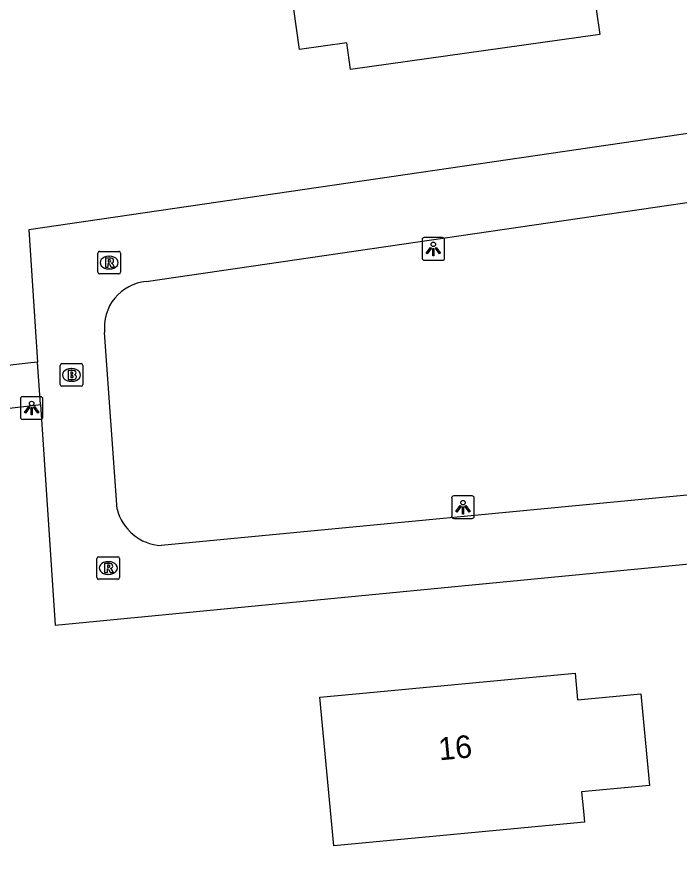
# Model space of a CAD drawing. Extents: x 162675 to 163482, y 379761 to 381227.
# Drawn here: x 163063.15 to 163092.42, y 380634.64 to 380672.29 of the extents above; entities that cross this region are included whole.
import ezdxf

# ---------------------------------------------------------------- set-up
doc = ezdxf.new("R2010")
doc.units = 0
for name, color, linetype in [('IMGEO_Brandkraan', 7, 'Continuous'), ('IMGEO_Lichtpunt', 7, 'Continuous'), ('IMGEO_Pand', 7, 'Continuous'), ('IMGEO_Pand_nummerreeks', 7, 'Continuous'), ('IMGEO_Rijbaan_lokaal_open', 7, 'Continuous'), ('IMGEO_Rioolput', 7, 'Continuous'), ('IMGEO_Voetpad_open', 7, 'Continuous')]:
    doc.layers.add(name, color=color, linetype=linetype)

msp = doc.modelspace()

# ---------------------------------------------------------------- linework, layer by layer
at = {"layer": 'IMGEO_Brandkraan'}
for p, q in [((163065.053, 380656.043), (163065.053, 380656.895)), ((163065.128, 380656.969), (163065.98, 380656.969)), ((163066.054, 380656.895), (163066.054, 380656.043)), ((163065.541, 380656.749), (163065.566, 380656.749)), ((163065.564, 380656.189), (163065.539, 380656.189)), ((163065.98, 380655.969), (163065.128, 380655.969))]:
    msp.add_line(p, q, dxfattribs=at)
for points in [[(163065.053, 380656.043), (163065.053, 380656.895)], [(163065.128, 380656.969), (163065.98, 380656.969)], [(163066.054, 380656.895), (163066.054, 380656.043)], [(163065.401, 380656.669), (163065.401, 380656.269), (163065.614, 380656.269)], [(163065.632, 380656.669), (163065.401, 380656.669)], [(163065.58, 380656.588), (163065.526, 380656.588), (163065.526, 380656.512)], [(163065.526, 380656.512), (163065.579, 380656.512)], [(163065.588, 380656.436), (163065.526, 380656.436), (163065.526, 380656.355)], [(163065.526, 380656.355), (163065.588, 380656.355)], [(163065.98, 380655.969), (163065.128, 380655.969)]]:
    msp.add_lwpolyline(points, dxfattribs=at)
for centre, radius, start, end in [((163065.13, 380656.893), 0.0765, 91.552, 178.448), ((163065.13, 380656.893), 0.0765, 91.552, 178.448), ((163065.978, 380656.893), 0.0765, 1.552, 88.448), ((163065.978, 380656.893), 0.0765, 1.552, 88.448), ((163065.581, 380656.55), 0.0379, 267.8285, 90.9355), ((163065.589, 380656.395), 0.0404, 269.8759, 90.5077), ((163065.636, 380656.524), 0.145, 59.4692, 91.5367), ((163065.661, 380656.571), 0.0922, 285.5137, 58.1501), ((163065.666, 380656.379), 0.105, 301.3115, 78.989), ((163065.13, 380656.045), 0.0765, 181.552, 268.448), ((163065.13, 380656.045), 0.0765, 181.552, 268.448), ((163065.62, 380656.52), 0.251, 268.6676, 293.5347), ((163065.978, 380656.045), 0.0765, 271.552, 358.448), ((163065.978, 380656.045), 0.0765, 271.552, 358.448)]:
    msp.add_arc(centre, radius, start, end, dxfattribs=at)
for centre, major_axis, ratio, start_param, end_param in [((163065.54, 380656.469), (-0.387, 0.002), 0.722429, 4.712389, 7.853982), ((163065.565, 380656.469), (-0.39, 0.002), 0.717154, 1.570796, 4.712389)]:
    msp.add_ellipse(centre, major_axis=major_axis, ratio=ratio, start_param=start_param, end_param=end_param, dxfattribs=at)
at = {"layer": 'IMGEO_Lichtpunt'}
for p, q in [((163081.032, 380662.444), (163081.032, 380661.637)), ((163081.032, 380662.444), (163081.032, 380661.637)), ((163081.934, 380662.539), (163081.126, 380662.539)), ((163081.934, 380662.539), (163081.126, 380662.539)), ((163082.028, 380661.637), (163082.028, 380662.444)), ((163082.028, 380661.637), (163082.028, 380662.444)), ((163081.126, 380661.543), (163081.934, 380661.543)), ((163081.126, 380661.543), (163081.934, 380661.543)), ((163063.295, 380655.414), (163063.295, 380654.607)), ((163063.295, 380655.414), (163063.295, 380654.607)), ((163064.197, 380655.509), (163063.389, 380655.509)), ((163064.197, 380655.509), (163063.389, 380655.509)), ((163064.291, 380654.607), (163064.291, 380655.414)), ((163064.291, 380654.607), (163064.291, 380655.414)), ((163063.389, 380654.513), (163064.197, 380654.513)), ((163063.389, 380654.513), (163064.197, 380654.513)), ((163083.241, 380651.126), (163082.433, 380651.126)), ((163083.241, 380651.126), (163082.433, 380651.126)), ((163082.339, 380651.031), (163082.339, 380650.224)), ((163082.339, 380651.031), (163082.339, 380650.224)), ((163083.335, 380650.224), (163083.335, 380651.031)), ((163083.335, 380650.224), (163083.335, 380651.031)), ((163082.433, 380650.13), (163083.241, 380650.13)), ((163082.433, 380650.13), (163083.241, 380650.13))]:
    msp.add_line(p, q, dxfattribs=at)
for points in [[(163081.406, 380662.108), (163081.445, 380662.08), (163081.257, 380661.818), (163081.219, 380661.845), (163081.406, 380662.108)], [(163081.508, 380662.06), (163081.555, 380662.06), (163081.555, 380661.738), (163081.508, 380661.738), (163081.508, 380662.06)], [(163081.618, 380662.08), (163081.656, 380662.107), (163081.843, 380661.845), (163081.804, 380661.817), (163081.618, 380662.08)], [(163063.669, 380655.078), (163063.708, 380655.05), (163063.52, 380654.788), (163063.482, 380654.815), (163063.669, 380655.078)], [(163063.771, 380655.03), (163063.818, 380655.03), (163063.818, 380654.708), (163063.771, 380654.708), (163063.771, 380655.03)], [(163063.881, 380655.05), (163063.919, 380655.077), (163064.106, 380654.815), (163064.067, 380654.787), (163063.881, 380655.05)], [(163082.713, 380650.695), (163082.752, 380650.667), (163082.564, 380650.405), (163082.526, 380650.432), (163082.713, 380650.695)], [(163082.815, 380650.647), (163082.862, 380650.647), (163082.862, 380650.325), (163082.815, 380650.325), (163082.815, 380650.647)], [(163082.925, 380650.667), (163082.963, 380650.694), (163083.15, 380650.432), (163083.111, 380650.404), (163082.925, 380650.667)]]:
    msp.add_lwpolyline(points, dxfattribs=at)
for centre in [(163081.531, 380662.242), (163063.794, 380655.212), (163082.838, 380650.829)]:
    msp.add_circle(centre, 0.0994, dxfattribs=at)
for centre, start, end in [((163081.126, 380662.444), 90, 180), ((163081.126, 380662.444), 90, 180), ((163081.934, 380662.444), 0, 90), ((163081.934, 380662.444), 0, 90), ((163081.126, 380661.637), 180, 270), ((163081.126, 380661.637), 180, 270), ((163081.934, 380661.637), 270, 0), ((163081.934, 380661.637), 270, 360), ((163063.389, 380655.414), 90, 180), ((163063.389, 380655.414), 90, 180), ((163064.197, 380655.414), 0, 90), ((163064.197, 380655.414), 0, 90), ((163063.389, 380654.607), 180, 270), ((163063.389, 380654.607), 180, 270), ((163064.197, 380654.607), 270, 0), ((163064.197, 380654.607), 270, 360), ((163082.433, 380651.031), 90, 180), ((163082.433, 380651.031), 90, 180), ((163083.241, 380651.031), 0, 90), ((163083.241, 380651.031), 0, 90), ((163082.433, 380650.224), 180, 270), ((163082.433, 380650.224), 180, 270), ((163083.241, 380650.224), 270, 0), ((163083.241, 380650.224), 270, 360)]:
    msp.add_arc(centre, 0.0946, start, end, dxfattribs=at)
at = {"layer": 'IMGEO_Pand'}
for points in [[(163076.967, 380676.192), (163076.556, 380679.109), (163082.364, 380679.928), (163082.776, 380677.011), (163088.02, 380677.751), (163087.739, 380679.747), (163090.667, 380680.16), (163091.508, 380674.192), (163088.561, 380673.776), (163088.88, 380671.518), (163077.877, 380669.967), (163077.711, 380671.146), (163075.622, 380670.852), (163075.001, 380675.266), (163077.057, 380675.555), (163076.967, 380676.192)], [(163077.138, 380635.654), (163076.519, 380642.231), (163078.108, 380642.381), (163087.787, 380643.295), (163087.898, 380642.117), (163090.688, 380642.381), (163091.07, 380638.329), (163088.076, 380638.046), (163088.157, 380637.192), (163088.204, 380636.699), (163077.138, 380635.654)]]:
    msp.add_lwpolyline(points, dxfattribs=at)
at = {"layer": 'IMGEO_Rijbaan_lokaal_open'}
for points in [[(163100.129, 380668.22), (163063.669, 380662.881), (163064.055, 380657.039)], [(163068.853, 380660.603), (163100.497, 380665.225)], [(163067.57, 380650.541), (163067.016, 380658.343)], [(163064.179, 380655.165), (163064.055, 380657.039)], [(163064.179, 380655.165), (163064.825, 380645.41), (163101.514, 380648.96)], [(163101.8, 380652.027), (163069.509, 380648.927)]]:
    msp.add_lwpolyline(points, dxfattribs=at)
for centre, radius, start, end in [((163069.042, 380658.573), 2.039, 95.3254, 186.464), ((163069.638, 380651.053), 2.13, 193.9175, 266.5354)]:
    msp.add_arc(centre, radius, start, end, dxfattribs=at)
at = {"layer": 'IMGEO_Rioolput'}
for p, q in [((163066.717, 380661.007), (163066.717, 380661.859)), ((163066.792, 380661.933), (163067.644, 380661.933)), ((163067.205, 380661.713), (163067.23, 380661.713)), ((163067.718, 380661.859), (163067.718, 380661.007)), ((163067.644, 380660.933), (163066.792, 380660.933)), ((163067.228, 380661.153), (163067.203, 380661.153)), ((163066.676, 380647.512), (163066.676, 380648.364)), ((163066.751, 380648.438), (163067.603, 380648.438)), ((163067.164, 380648.218), (163067.189, 380648.218)), ((163067.677, 380648.364), (163067.677, 380647.512)), ((163067.603, 380647.438), (163066.751, 380647.438)), ((163067.187, 380647.658), (163067.162, 380647.658))]:
    msp.add_line(p, q, dxfattribs=at)
for points in [[(163066.717, 380661.007), (163066.717, 380661.859)], [(163066.792, 380661.933), (163067.644, 380661.933)], [(163067.718, 380661.859), (163067.718, 380661.007)], [(163067.306, 380661.631), (163067.054, 380661.633), (163067.054, 380661.233)], [(163067.054, 380661.233), (163067.178, 380661.233), (163067.178, 380661.395), (163067.189, 380661.395)], [(163067.232, 380661.552), (163067.178, 380661.552), (163067.178, 380661.471)], [(163067.178, 380661.471), (163067.23, 380661.471)], [(163067.236, 380661.366), (163067.307, 380661.233), (163067.447, 380661.233), (163067.382, 380661.359)], [(163067.644, 380660.933), (163066.792, 380660.933)], [(163066.676, 380647.512), (163066.676, 380648.364)], [(163066.751, 380648.438), (163067.603, 380648.438)], [(163067.265, 380648.136), (163067.013, 380648.138), (163067.013, 380647.738)], [(163067.677, 380648.364), (163067.677, 380647.512)], [(163067.013, 380647.738), (163067.137, 380647.738), (163067.137, 380647.9), (163067.148, 380647.9)], [(163067.191, 380648.057), (163067.137, 380648.057), (163067.137, 380647.976)], [(163067.137, 380647.976), (163067.189, 380647.976)], [(163067.195, 380647.871), (163067.266, 380647.738), (163067.406, 380647.738), (163067.341, 380647.864)], [(163067.603, 380647.438), (163066.751, 380647.438)]]:
    msp.add_lwpolyline(points, dxfattribs=at)
for centre, radius, start, end in [((163066.794, 380661.857), 0.0765, 91.552, 178.448), ((163066.794, 380661.857), 0.0765, 91.552, 178.448), ((163067.642, 380661.857), 0.0765, 1.552, 88.448), ((163067.642, 380661.857), 0.0765, 1.552, 88.448), ((163067.188, 380661.342), 0.0533, 26.0293, 88.6989), ((163067.214, 380661.66), 0.19, 274.7715, 282.9687), ((163067.238, 380661.456), 0.0964, 77.0061, 93.1865), ((163067.252, 380661.513), 0.0378, 276.6634, 79.6772), ((163067.305, 380661.521), 0.109, 350.3612, 89.416), ((163067.303, 380661.521), 0.112, 277.5842, 350.9817), ((163067.287, 380661.306), 0.108, 29.5134, 73.7905), ((163066.794, 380661.009), 0.0765, 181.552, 268.448), ((163066.794, 380661.009), 0.0765, 181.552, 268.448), ((163067.642, 380661.009), 0.0765, 271.552, 358.448), ((163067.642, 380661.009), 0.0765, 271.552, 358.448), ((163066.753, 380648.362), 0.0765, 91.552, 178.448), ((163066.753, 380648.362), 0.0765, 91.552, 178.448), ((163067.264, 380648.026), 0.109, 350.3612, 89.416), ((163067.601, 380648.362), 0.0765, 1.552, 88.448), ((163067.601, 380648.362), 0.0765, 1.552, 88.448), ((163067.147, 380647.847), 0.0533, 26.0293, 88.6989), ((163067.173, 380648.165), 0.19, 274.7715, 282.9687), ((163067.197, 380647.961), 0.0964, 77.0061, 93.1865), ((163067.211, 380648.018), 0.0378, 276.6634, 79.6772), ((163067.262, 380648.026), 0.112, 277.5842, 350.9817), ((163067.246, 380647.811), 0.108, 29.5134, 73.7905), ((163066.753, 380647.514), 0.0765, 181.552, 268.448), ((163066.753, 380647.514), 0.0765, 181.552, 268.448), ((163067.601, 380647.514), 0.0765, 271.552, 358.448), ((163067.601, 380647.514), 0.0765, 271.552, 358.448)]:
    msp.add_arc(centre, radius, start, end, dxfattribs=at)
for centre, major_axis, ratio, start_param, end_param in [((163067.204, 380661.433), (-0.387, 0.002), 0.722429, 4.712389, 7.853982), ((163067.229, 380661.433), (-0.39, 0.002), 0.717154, 1.570796, 4.712389), ((163067.163, 380647.938), (-0.387, 0.002), 0.722429, 4.712389, 7.853982), ((163067.188, 380647.938), (-0.39, 0.002), 0.717154, 1.570796, 4.712389)]:
    msp.add_ellipse(centre, major_axis=major_axis, ratio=ratio, start_param=start_param, end_param=end_param, dxfattribs=at)
at = {"layer": 'IMGEO_Voetpad_open'}
for points in [[(163064.055, 380657.039), (163063.757, 380657.004), (163037.315, 380653.943), (163032.944, 380715.524), (163058.632, 380719.002), (163058.898, 380719.038)], [(163067.753, 380591.633), (163041.973, 380588.769), (163037.446, 380652.111), (163063.957, 380655.14), (163064.179, 380655.165)]]:
    msp.add_lwpolyline(points, dxfattribs=at)

# ---------------------------------------------------------------- texts
at = {"layer": 'IMGEO_Pand_nummerreeks'}
msp.add_text('16', height=1, rotation=5.3915, dxfattribs=at).set_placement((163081.796, 380639.435))

doc.saveas('drawing.dxf')
